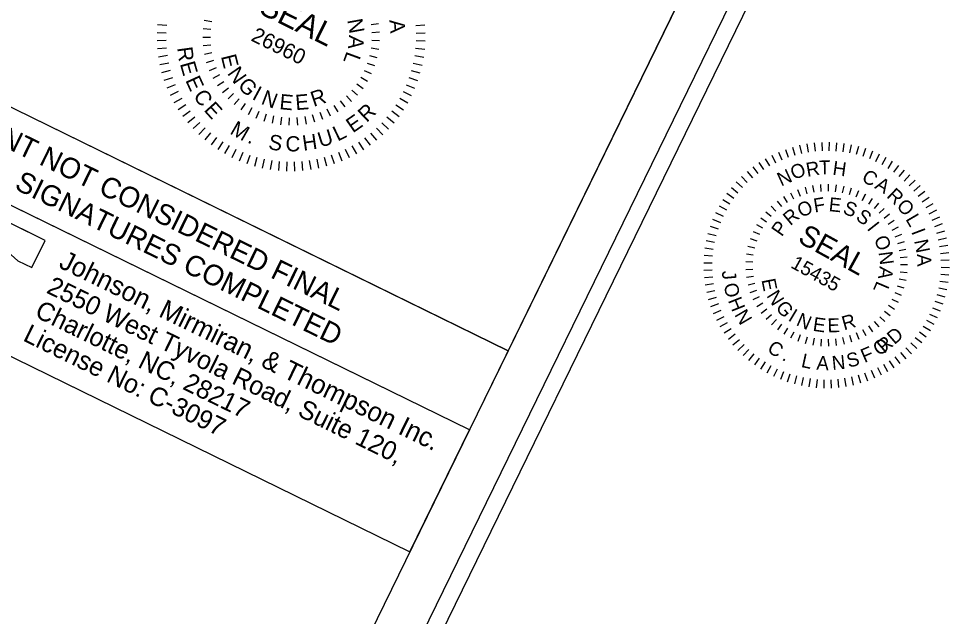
# Model space of a CAD drawing. Extents: x 1518400 to 1523182, y 633375 to 639930.
# Drawn here: x 1522685.9 to 1523182.2, y 634928.7 to 635247.1 of the extents above; entities that cross this region are included whole.
import ezdxf

# ---------------------------------------------------------------- set-up
doc = ezdxf.new("R2010")
doc.units = 0
for name, color, linetype in [('Default', 7, 'Continuous'), ('Old_Level_21', 7, 'Continuous'), ('Sheet Plan CELL', 7, 'Continuous'), ('Sheet Plot Border Inside CELL', 7, 'Continuous'), ('Sheet Plot Border Outside CELL', 7, 'Continuous'), ('Sheet Sticker Exception Certification CELL', 7, 'Continuous')]:
    doc.layers.add(name, color=color, linetype=linetype)

msp = doc.modelspace()

# ---------------------------------------------------------------- linework, layer by layer
at = {"layer": 'Default'}
for p, q in [((1522784.95, 635246.32), (1522788.94, 635245.55)), ((1522760.03, 635244.08), (1522764.89, 635243.63)), ((1522784.31, 635241.81), (1522788.36, 635241.43)), ((1522877.89, 635244.39), (1522873.86, 635243.78)), ((1522902.51, 635243.7), (1522897.66, 635243.27)), ((1522759.75, 635235.45), (1522764.63, 635235.58)), ((1522759.77, 635239.77), (1522764.64, 635239.61)), ((1522784.12, 635237.26), (1522788.17, 635237.28)), ((1522878.34, 635239.86), (1522874.28, 635239.64)), ((1522878.36, 635235.3), (1522874.29, 635235.48)), ((1522902.74, 635235.06), (1522897.88, 635235.23)), ((1522902.76, 635239.38), (1522897.89, 635239.25)), ((1522760, 635231.13), (1522764.86, 635231.57)), ((1522784.35, 635232.72), (1522788.39, 635233.11)), ((1522877.93, 635230.76), (1522873.9, 635231.34)), ((1522902.48, 635230.75), (1522897.62, 635231.2)), ((1522760.51, 635226.84), (1522765.33, 635227.57)), ((1522785.02, 635228.2), (1522789.01, 635229)), ((1522877.07, 635226.29), (1522873.12, 635227.25)), ((1522901.95, 635226.47), (1522897.12, 635227.22)), ((1522761.28, 635222.6), (1522766.04, 635223.6)), ((1522786.13, 635223.79), (1522790.01, 635224.96)), ((1522787.65, 635219.5), (1522791.41, 635221.04)), ((1522875.78, 635221.92), (1522871.95, 635223.26)), ((1522901.15, 635222.21), (1522896.39, 635223.26)), ((1522762.3, 635218.39), (1522767, 635219.69)), ((1522763.58, 635214.27), (1522768.19, 635215.84)), ((1522789.59, 635215.37), (1522793.17, 635217.27)), ((1522871.97, 635213.65), (1522868.47, 635215.7)), ((1522874.08, 635217.69), (1522870.39, 635219.39)), ((1522898.81, 635213.9), (1522894.21, 635215.51)), ((1522900.11, 635218.02), (1522895.42, 635219.35)), ((1522765.1, 635210.22), (1522769.6, 635212.07)), ((1522791.91, 635211.45), (1522795.3, 635213.69)), ((1522794.6, 635207.77), (1522797.76, 635210.33)), ((1522866.28, 635212.33), (1522869.58, 635209.96)), ((1522897.27, 635209.87), (1522892.77, 635211.75)), ((1522766.86, 635206.27), (1522771.25, 635208.4)), ((1522797.63, 635204.37), (1522800.53, 635207.22)), ((1522863.48, 635203), (1522860.7, 635205.96)), ((1522866.65, 635206.27), (1522863.6, 635208.95)), ((1522895.48, 635205.93), (1522891.11, 635208.08)), ((1522768.86, 635202.45), (1522773.11, 635204.83)), ((1522771.08, 635198.74), (1522775.18, 635201.37)), ((1522803.57, 635204.41), (1522800.95, 635201.3)), ((1522804.61, 635198.53), (1522806.9, 635201.88)), ((1522856.27, 635197.46), (1522854.11, 635200.89)), ((1522860, 635200.06), (1522857.53, 635203.28)), ((1522891.22, 635198.42), (1522887.13, 635201.07)), ((1522893.46, 635202.11), (1522889.22, 635204.51)), ((1522773.53, 635195.18), (1522777.46, 635198.06)), ((1522808.48, 635196.13), (1522810.44, 635199.7)), ((1522812.57, 635194.13), (1522814.19, 635197.86)), ((1522816.84, 635192.53), (1522818.08, 635196.4)), ((1522843.8, 635191.97), (1522842.71, 635195.89)), ((1522848.12, 635193.4), (1522846.67, 635197.18)), ((1522852.29, 635195.22), (1522850.48, 635198.86)), ((1522888.76, 635194.87), (1522884.84, 635197.77)), ((1522776.19, 635191.77), (1522779.93, 635194.88)), ((1522779.04, 635188.52), (1522782.6, 635191.86)), ((1522821.24, 635191.35), (1522822.1, 635195.33)), ((1522825.73, 635190.6), (1522826.2, 635194.64)), ((1522830.27, 635190.29), (1522830.36, 635194.35)), ((1522834.83, 635190.41), (1522834.52, 635194.46)), ((1522839.35, 635190.97), (1522838.65, 635194.97)), ((1522883.21, 635188.24), (1522879.66, 635191.6)), ((1522886.09, 635191.48), (1522882.35, 635194.6)), ((1522782.08, 635185.46), (1522785.44, 635189.01)), ((1522785.32, 635182.59), (1522788.44, 635186.33)), ((1522876.9, 635182.35), (1522873.79, 635186.1)), ((1522880.15, 635185.2), (1522876.82, 635188.76)), ((1522788.71, 635179.91), (1522791.6, 635183.83)), ((1522792.26, 635177.46), (1522794.91, 635181.54)), ((1522869.93, 635177.24), (1522867.3, 635181.35)), ((1522873.5, 635179.69), (1522870.62, 635183.63)), ((1522795.95, 635175.21), (1522798.35, 635179.45)), ((1522799.77, 635173.19), (1522801.92, 635177.57)), ((1522803.71, 635171.4), (1522805.59, 635175.9)), ((1522858.45, 635171.26), (1522856.6, 635175.77)), ((1522862.4, 635173.02), (1522860.28, 635177.41)), ((1522866.23, 635175.02), (1522863.85, 635179.27)), ((1522807.74, 635169.86), (1522809.35, 635174.46)), ((1522811.86, 635168.56), (1522813.18, 635173.25)), ((1522816.05, 635167.52), (1522817.09, 635172.28)), ((1522820.3, 635166.72), (1522821.06, 635171.55)), ((1522824.59, 635166.19), (1522825.04, 635171.05)), ((1522828.9, 635165.93), (1522829.07, 635170.8)), ((1522833.22, 635165.91), (1522833.09, 635170.79)), ((1522837.54, 635166.16), (1522837.11, 635171.02)), ((1522841.83, 635166.67), (1522841.11, 635171.49)), ((1522846.08, 635167.44), (1522845.07, 635172.21)), ((1522850.28, 635168.46), (1522848.98, 635173.16)), ((1522854.41, 635169.74), (1522852.83, 635174.35)), ((1522700.09, 635129), (1522664.71, 635146.26)), ((1522693.02, 635114.5), (1522700.09, 635129)), ((1522685.49, 635118.17), (1522693.02, 635114.5))]:
    msp.add_line(p, q, dxfattribs=at)
msp.add_lwpolyline([(1522535.19, 635138.9), (1522894.58, 634963.13), (1522926.3, 635027.99), (1522566.91, 635203.76)], close=True, dxfattribs=at)
msp.add_lwpolyline([(1522700.09, 635129), (1522664.71, 635146.26), (1522661.54, 635139.76), (1522661.45, 635139.56), (1522685.49, 635118.17), (1522693.02, 635114.5), (1522700.09, 635129)], dxfattribs=at)
at = {"layer": 'Old_Level_21'}
for p, q in [((1523110.16, 635180.92), (1523110.61, 635176.48)), ((1523114.11, 635181.2), (1523114.29, 635176.73)), ((1523118.07, 635181.23), (1523117.97, 635176.77)), ((1523122.02, 635181.03), (1523121.65, 635176.58)), ((1523125.95, 635180.6), (1523125.32, 635176.17)), ((1523091.07, 635176.01), (1523092.82, 635171.91)), ((1523094.76, 635177.45), (1523096.26, 635173.25)), ((1523098.52, 635178.66), (1523099.76, 635174.38)), ((1523102.35, 635179.65), (1523103.33, 635175.3)), ((1523106.24, 635180.4), (1523106.95, 635176)), ((1523129.84, 635179.92), (1523128.95, 635175.54)), ((1523133.7, 635179.01), (1523132.54, 635174.7)), ((1523137.49, 635177.87), (1523136.07, 635173.64)), ((1523141.19, 635176.5), (1523139.53, 635172.37)), ((1523084, 635172.48), (1523086.22, 635168.61)), ((1523087.48, 635174.35), (1523089.47, 635170.36)), ((1523144.82, 635174.91), (1523142.9, 635170.88)), ((1523148.34, 635173.11), (1523146.19, 635169.2)), ((1523151.75, 635171.1), (1523149.36, 635167.32)), ((1523077.4, 635168.12), (1523080.08, 635164.55)), ((1523080.63, 635170.4), (1523083.09, 635166.68)), ((1523155.02, 635168.88), (1523152.42, 635165.26)), ((1523158.16, 635166.47), (1523155.34, 635163.02)), ((1523071.37, 635163.01), (1523074.47, 635159.78)), ((1523074.3, 635165.65), (1523077.2, 635162.25)), ((1523161.15, 635163.88), (1523158.12, 635160.6)), ((1523163.98, 635161.11), (1523160.75, 635158.01)), ((1523066.01, 635157.19), (1523069.46, 635154.37)), ((1523068.6, 635160.17), (1523071.88, 635157.15)), ((1523101.27, 635156.06), (1523102.6, 635152.58)), ((1523105.23, 635157.36), (1523106.22, 635153.77)), ((1523109.3, 635158.28), (1523109.94, 635154.61)), ((1523113.44, 635158.8), (1523113.72, 635155.08)), ((1523117.61, 635158.91), (1523117.53, 635155.19)), ((1523121.77, 635158.63), (1523121.33, 635154.93)), ((1523125.89, 635157.94), (1523125.09, 635154.3)), ((1523129.91, 635156.85), (1523128.77, 635153.31)), ((1523166.63, 635158.18), (1523163.22, 635155.28)), ((1523061.39, 635150.78), (1523065.16, 635148.39)), ((1523063.6, 635154.05), (1523067.22, 635151.44)), ((1523093.82, 635152.34), (1523095.79, 635149.18)), ((1523097.45, 635154.38), (1523099.11, 635151.04)), ((1523133.81, 635155.39), (1523132.34, 635151.98)), ((1523137.56, 635153.56), (1523135.77, 635150.3)), ((1523135.77, 635150.3), (1523137.56, 635153.56)), ((1523141.11, 635151.37), (1523139.01, 635148.3)), ((1523169.09, 635155.08), (1523165.53, 635152.4)), ((1523171.38, 635151.85), (1523167.65, 635149.39)), ((1523059.37, 635147.37), (1523063.28, 635145.21)), ((1523087.21, 635147.25), (1523089.76, 635144.54)), ((1523090.39, 635149.95), (1523092.66, 635147.01)), ((1523144.44, 635148.85), (1523142.05, 635145.99)), ((1523147.5, 635146.02), (1523144.85, 635143.41)), ((1523173.46, 635148.48), (1523169.59, 635146.26)), ((1523057.57, 635143.84), (1523061.6, 635141.93)), ((1523081.71, 635140.99), (1523084.73, 635138.83)), ((1523084.31, 635144.26), (1523087.11, 635141.8)), ((1523150.28, 635142.91), (1523147.39, 635140.57)), ((1523175.33, 635145), (1523171.33, 635143.01)), ((1523176.98, 635141.41), (1523172.88, 635139.66)), ((1523054.61, 635136.51), (1523058.84, 635135.1)), ((1523055.98, 635140.22), (1523060.11, 635138.55)), ((1523079.44, 635137.5), (1523082.65, 635135.62)), ((1523152.74, 635139.54), (1523149.64, 635137.49)), ((1523154.87, 635135.96), (1523151.58, 635134.21)), ((1523178.42, 635137.72), (1523174.22, 635136.22)), ((1523053.47, 635132.73), (1523057.78, 635131.56)), ((1523077.51, 635133.8), (1523080.89, 635132.24)), ((1523156.65, 635132.18), (1523153.2, 635130.76)), ((1523179.64, 635133.96), (1523175.35, 635132.72)), ((1523052.56, 635128.87), (1523056.94, 635127.97)), ((1523075.96, 635129.93), (1523079.47, 635128.71)), ((1523158.04, 635128.25), (1523154.48, 635127.17)), ((1523180.62, 635130.13), (1523176.27, 635129.15)), ((1523181.37, 635126.24), (1523176.97, 635125.53)), ((1523051.45, 635121.04), (1523055.9, 635120.68)), ((1523051.88, 635124.98), (1523056.31, 635124.35)), ((1523073.99, 635121.83), (1523077.67, 635121.3)), ((1523074.77, 635125.92), (1523078.39, 635125.05)), ((1523159.05, 635124.21), (1523155.41, 635123.48)), ((1523181.89, 635122.32), (1523177.45, 635121.87)), ((1523051.25, 635117.09), (1523055.71, 635117)), ((1523073.61, 635117.68), (1523077.32, 635117.52)), ((1523159.68, 635120.08), (1523155.97, 635119.7)), ((1523182.17, 635118.37), (1523177.71, 635118.19)), ((1523051.28, 635113.13), (1523055.75, 635113.32)), ((1523073.62, 635113.51), (1523077.33, 635113.7)), ((1523159.71, 635111.75), (1523156, 635112.09)), ((1523159.89, 635115.92), (1523156.17, 635115.9)), ((1523182.21, 635114.41), (1523177.74, 635114.51)), ((1523051.56, 635109.19), (1523056, 635109.64)), ((1523074.03, 635109.36), (1523077.72, 635109.91)), ((1523074.86, 635105.27), (1523078.46, 635106.17)), ((1523159.11, 635107.62), (1523155.46, 635108.33)), ((1523181.57, 635106.53), (1523177.14, 635107.16)), ((1523182, 635110.46), (1523177.56, 635110.83)), ((1523052.08, 635105.27), (1523056.48, 635105.98)), ((1523052.83, 635101.38), (1523057.19, 635102.36)), ((1523076.06, 635101.28), (1523079.57, 635102.53)), ((1523158.14, 635103.57), (1523154.57, 635104.62)), ((1523180.9, 635102.64), (1523176.52, 635103.53)), ((1523053.82, 635097.55), (1523058.1, 635098.79)), ((1523077.65, 635097.42), (1523081.02, 635099)), ((1523155.02, 635095.84), (1523151.72, 635097.55)), ((1523156.76, 635099.63), (1523153.32, 635101.02)), ((1523178.84, 635094.99), (1523174.61, 635096.41)), ((1523179.98, 635098.78), (1523175.67, 635099.94)), ((1523055.03, 635093.79), (1523059.23, 635095.28)), ((1523056.47, 635090.1), (1523060.57, 635091.85)), ((1523079.6, 635093.74), (1523082.8, 635095.63)), ((1523081.9, 635090.25), (1523084.91, 635092.45)), ((1523147.65, 635091.27), (1523150.57, 635088.96)), ((1523152.92, 635092.23), (1523149.8, 635094.26)), ((1523177.47, 635091.29), (1523173.34, 635092.95)), ((1523058.13, 635086.51), (1523062.12, 635088.5)), ((1523084.53, 635087.01), (1523087.31, 635089.49)), ((1523089.95, 635086.79), (1523087.43, 635084.05)), ((1523147.73, 635085.71), (1523145.06, 635088.3)), ((1523174.08, 635084.14), (1523170.17, 635086.29)), ((1523175.89, 635087.66), (1523171.86, 635089.58)), ((1523060, 635083.03), (1523063.87, 635085.25)), ((1523062.08, 635079.66), (1523065.8, 635082.12)), ((1523090.65, 635081.36), (1523092.89, 635084.32)), ((1523094.09, 635079), (1523096.03, 635082.17)), ((1523137.85, 635078.11), (1523136.02, 635081.35)), ((1523141.38, 635080.33), (1523139.26, 635083.38)), ((1523144.68, 635082.86), (1523142.27, 635085.7)), ((1523172.07, 635080.73), (1523168.3, 635083.12)), ((1523064.36, 635076.43), (1523067.93, 635079.11)), ((1523097.74, 635076.99), (1523099.38, 635080.33)), ((1523101.57, 635075.34), (1523102.88, 635078.82)), ((1523105.54, 635074.07), (1523106.5, 635077.66)), ((1523109.61, 635073.18), (1523110.23, 635076.85)), ((1523113.76, 635072.7), (1523114.02, 635076.41)), ((1523117.93, 635072.61), (1523117.83, 635076.33)), ((1523122.09, 635072.93), (1523121.63, 635076.61)), ((1523126.2, 635073.64), (1523125.38, 635077.27)), ((1523130.22, 635074.76), (1523129.06, 635078.28)), ((1523134.11, 635076.24), (1523132.61, 635079.65)), ((1523167.45, 635074.32), (1523163.99, 635077.14)), ((1523169.85, 635077.46), (1523166.23, 635080.06)), ((1523066.83, 635073.33), (1523070.23, 635076.23)), ((1523069.47, 635070.4), (1523072.7, 635073.5)), ((1523162.08, 635068.5), (1523158.98, 635071.73)), ((1523164.85, 635071.33), (1523161.57, 635074.36)), ((1523072.31, 635067.63), (1523075.33, 635070.91)), ((1523075.29, 635065.03), (1523078.11, 635068.49)), ((1523156.05, 635063.39), (1523153.37, 635066.95)), ((1523159.15, 635065.85), (1523156.26, 635069.26)), ((1523078.43, 635062.63), (1523081.04, 635066.25)), ((1523081.71, 635060.41), (1523084.09, 635064.19)), ((1523085.11, 635058.4), (1523087.27, 635062.31)), ((1523149.45, 635059.02), (1523147.23, 635062.89)), ((1523152.82, 635061.11), (1523150.36, 635064.83)), ((1523088.64, 635056.59), (1523090.55, 635060.62)), ((1523092.26, 635055.01), (1523093.93, 635059.14)), ((1523095.97, 635053.64), (1523097.38, 635057.87)), ((1523099.75, 635052.5), (1523100.92, 635056.81)), ((1523134.93, 635052.85), (1523133.69, 635057.13)), ((1523138.69, 635054.06), (1523137.2, 635058.26)), ((1523142.38, 635055.5), (1523140.63, 635059.6)), ((1523145.97, 635057.15), (1523143.98, 635061.15)), ((1523103.61, 635051.58), (1523104.51, 635055.96)), ((1523107.5, 635050.91), (1523108.13, 635055.34)), ((1523111.44, 635050.48), (1523111.8, 635054.92)), ((1523115.39, 635050.27), (1523115.48, 635054.74)), ((1523119.35, 635050.31), (1523119.16, 635054.77)), ((1523123.29, 635050.59), (1523122.84, 635055.03)), ((1523127.21, 635051.11), (1523126.5, 635055.51)), ((1523131.1, 635051.86), (1523130.12, 635056.21))]:
    msp.add_line(p, q, dxfattribs=at)
at = {"layer": 'Sheet Plan CELL'}
for points in [[(1523067.8, 635317.31), (1520372.85, 636635.35), (1519450.22, 634748.89), (1522145.17, 633430.84)], [(1522686.38, 635448.09), (1523045.79, 635272.3), (1522946.94, 635070.18), (1522587.52, 635245.97)], [(1522686.38, 635448.09), (1523045.79, 635272.3), (1522946.95, 635070.21), (1522587.53, 635245.99)]]:
    msp.add_lwpolyline(points, close=True, dxfattribs=at)
at = {"layer": 'Sheet Plot Border Inside CELL'}
msp.add_lwpolyline([(1519172.24, 634879.28), (1522165.43, 633415.37), (1523092.46, 635310.82), (1520099.27, 636774.73)], close=True, dxfattribs=at)
at = {"layer": 'Sheet Plot Border Outside CELL'}
msp.add_lwpolyline([(1519131.31, 634854.77), (1522155.94, 633375.48), (1523118.12, 635342.8), (1520093.48, 636822.08)], close=True, dxfattribs=at)
at = {"layer": 'Sheet Sticker Exception Certification CELL'}
for p, q in [((1522587.56, 635245.98), (1522946.95, 635070.21)), ((1522926.3, 635027.99), (1522566.91, 635203.76)), ((1522946.94, 635070.18), (1522926.29, 635027.96))]:
    msp.add_line(p, q, dxfattribs=at)

# ---------------------------------------------------------------- texts
at = {"layer": 'Default'}
for s, height, rotation, p in [('SEAL', 12.189, 333.8847, (1522813.26, 635250.31)), ('N', 8.12, 280.3478, (1522861.1, 635246.39)), ('A', 8.12, 274.4018, (1522883.62, 635246.35)), ('26960', 8.119, 333.8847, (1522809.33, 635235.6)), ('A', 8.12, 265.0516, (1522862.17, 635238.46)), ('R', 8.12, 277.8197, (1522770.45, 635231.59)), ('E', 8.12, 283.9548, (1522793.77, 635227.07)), ('L', 8.12, 249.7554, (1522860.99, 635230.09)), ('E', 8.12, 285.8915, (1522771.88, 635223.08)), ('N', 8.12, 304.8099, (1522796.92, 635217.99)), ('E', 8.12, 294.5343, (1522774.71, 635214.32)), ('G', 8.12, 313.5761, (1522802.38, 635211.08)), ('I', 8.12, 331.6709, (1522809.92, 635204.48)), ('C', 8.12, 303.2069, (1522778.82, 635206.09)), ('N', 8.12, 339.3006, (1522814.75, 635201.82)), ('E', 8.12, 354.6926, (1522824.78, 635198.92)), ('E', 8.12, 4.6785, (1522833.78, 635198.36)), ('R', 8.12, 18.4496, (1522843.22, 635200.04)), ('E', 8.12, 312.1794, (1522784.37, 635198.27)), ('R', 8.12, 43.5571, (1522871.51, 635191.48)), ('E', 8.12, 34.8844, (1522864.14, 635185.95)), ('M', 8.12, 329.9747, (1522798.11, 635186.08)), ('H', 8.12, 8.3265, (1522837.82, 635176.7)), ('U', 8.12, 17.2091, (1522846.87, 635178.37)), ('L', 8.12, 26.0918, (1522856.03, 635181.6)), ('.', 8.12, 337.717, (1522807.52, 635181.19)), ('S', 8.12, 350.5013, (1522818.72, 635177.64)), ('C', 8.12, 359.5039, (1522828.23, 635176.41)), ('Johnson, Mirmiran, & Thompson Inc.', 10.2224, 333.9377, (1522706.79, 635114.76)), ('2550 West Tyvola Road, Suite 120,', 9.9303, 333.9377, (1522700.2, 635101.29)), ('Charlotte, NC, 28217', 9.9303, 333.9377, (1522693.96, 635088.54)), ('License No: C-3097', 9.9303, 333.9377, (1522687.73, 635075.79))]:
    msp.add_text(s, height=height, rotation=rotation, dxfattribs=at).set_placement(p)
at = {"layer": 'Old_Level_21'}
for s, height, rotation, p in [('R', 7.43, 9.7975, (1523106.45, 635162.84)), ('T', 7.43, 1.6366, (1523112.84, 635164.07)), ('H', 7.43, 352.2046, (1523119.64, 635164.01)), ('N', 7.43, 24.8137, (1523092.54, 635157.61)), ('O', 7.43, 22.8543, (1523099.32, 635161.05)), ('C', 7.43, 328.4939, (1523134.9, 635161.05)), ('A', 7.43, 328.4939, (1523141.95, 635157)), ('R', 7.43, 316.4846, (1523148.32, 635152.24)), ('F', 7.43, 9.3776, (1523110.41, 635143.79)), ('E', 7.43, 354.0813, (1523117.65, 635144.6)), ('O', 7.43, 24.6738, (1523103.19, 635140.93)), ('S', 7.43, 338.7851, (1523125, 635143.47)), ('O', 7.43, 313.4278, (1523153.59, 635146.89)), ('R', 7.43, 39.9701, (1523097.39, 635136.5)), ('S', 7.43, 323.4888, (1523131.8, 635140.43)), ('L', 7.43, 300.2915, (1523158.62, 635140.34)), ('P', 7.43, 55.2663, (1523092.85, 635130.59)), ('SEAL', 11.16, 331.137, (1523100.83, 635128.34)), ('I', 7.43, 308.1926, (1523137.95, 635135.21)), ('O', 7.43, 292.8963, (1523141.8, 635129.78)), ('I', 7.43, 290.7161, (1523161.78, 635133.66)), ('N', 7.43, 281.4216, (1523163.35, 635128.8)), ('N', 7.43, 277.6001, (1523144.41, 635122.65)), ('A', 7.43, 271.6541, (1523165, 635121.62)), ('15435', 7.434, 331.137, (1523097.15, 635114.75)), ('J', 7.43, 275.072, (1523060.9, 635112.63)), ('A', 7.43, 262.3039, (1523145.04, 635115.35)), ('O', 7.43, 283.1438, (1523061.76, 635105.39)), ('E', 7.43, 281.2071, (1523081.99, 635107.94)), ('L', 7.43, 247.0076, (1523143.6, 635107.74)), ('N', 7.43, 302.0621, (1523084.47, 635099.5)), ('H', 7.43, 291.7865, (1523064.05, 635096.98)), ('G', 7.43, 310.8284, (1523089.16, 635092.93)), ('N', 7.43, 300.4591, (1523067.4, 635089.4)), ('I', 7.43, 328.9232, (1523095.77, 635086.57)), ('N', 7.43, 336.5528, (1523100.06, 635083.92)), ('E', 7.43, 351.9449, (1523109.11, 635080.83)), ('E', 7.43, 1.9308, (1523117.32, 635079.92)), ('R', 7.43, 15.7019, (1523126.03, 635081.04)), (' RD', 7.434, 40.8094, (1523145.38, 635066.67)), ('C', 7.43, 327.2269, (1523084.56, 635070.01)), ('F', 7.43, 23.344, (1523136.93, 635063.62)), ('O ', 7.434, 32.1366, (1523144.42, 635067.17)), ('L', 7.43, 347.7536, (1523102.81, 635061.6)), ('A', 7.43, 356.7561, (1523111.17, 635060.1)), ('N', 7.43, 5.5788, (1523119.89, 635059.92)), ('S', 7.43, 14.4614, (1523128.47, 635061.08)), ('.', 7.43, 334.9693, (1523092.55, 635065.38))]:
    msp.add_text(s, height=height, rotation=rotation, dxfattribs=at).set_placement(p)
at = {"layer": 'Sheet Sticker Exception Certification CELL'}
for s, p in [('DOCUMENT NOT CONSIDERED FINAL', (1522616.32, 635208.88)), ('UNLESS ALL SIGNATURES COMPLETED', (1522599.48, 635197.52))]:
    msp.add_text(s, height=11, rotation=333.9377, dxfattribs=at).set_placement(p)

doc.saveas('drawing.dxf')
